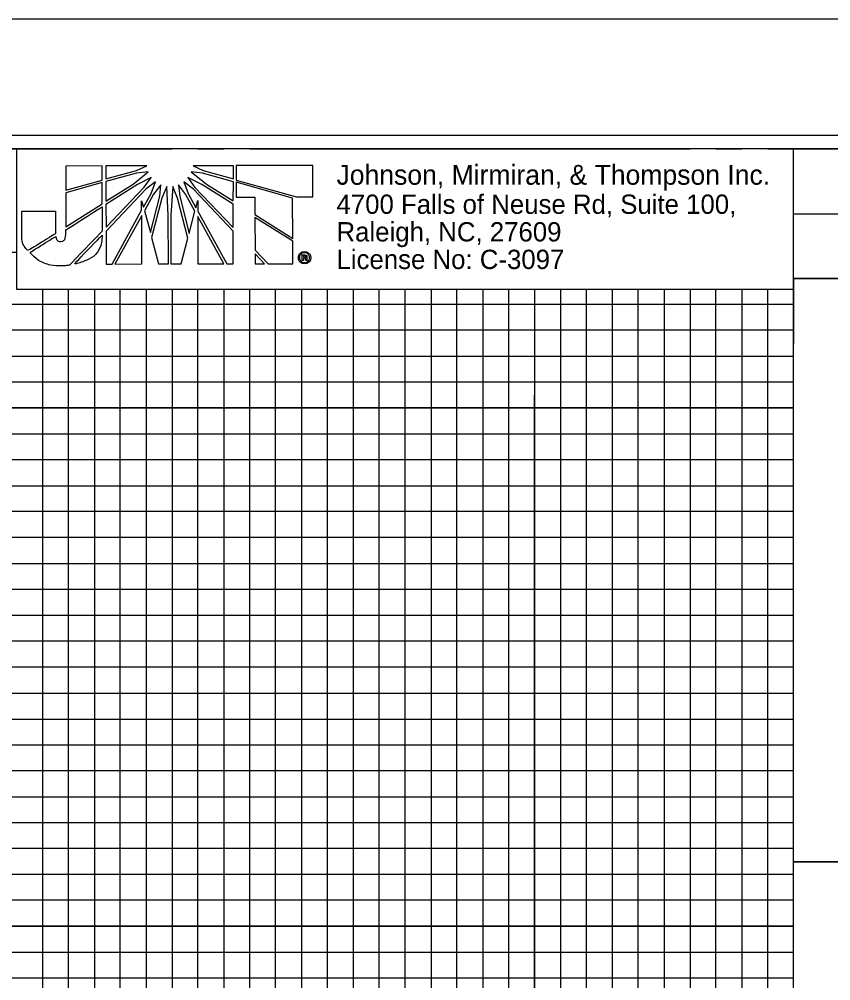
# Model space of a CAD drawing. Extents: x 1648862 to 1650889, y 802691 to 803791.
# Drawn here: x 1650179.8 to 1650336.5, y 803605.5 to 803791 of the extents above; entities that cross this region are included whole.
import ezdxf

# ---------------------------------------------------------------- set-up
doc = ezdxf.new("R2010")
doc.units = 0
for name, color, linetype in [('Prop Dimension Text', 7, 'Continuous'), ('Sheet Cutting Line CELL', 7, 'Continuous'), ('Sheet DOT Grid CELL', 7, 'Continuous'), ('Sheet Plan CELL', 7, 'Continuous'), ('Sheet Plot Border Inside CELL', 7, 'Continuous'), ('Sheet Plot Border Outside CELL', 7, 'Continuous'), ('Sheet Profile CELL', 7, 'Continuous'), ('Sheet Profile Grid Major CELL', 7, 'Continuous'), ('Sheet Profile Grid Middle CELL', 7, 'Continuous'), ('Sheet Profile Grid Minor CELL', 7, 'Continuous'), ('Sheet Sticker Exception Certification CELL', 7, 'Continuous')]:
    doc.layers.add(name, color=color, linetype=linetype)

msp = doc.modelspace()

# ---------------------------------------------------------------- linework, layer by layer
at = {"layer": 'Prop Dimension Text'}
for p, q in [((1650195.79, 803762.71), (1650188.77, 803762.7)), ((1650188.77, 803762.7), (1650188.77, 803758.05)), ((1650195.79, 803760), (1650195.79, 803762.71)), ((1650204.41, 803762.75), (1650196.52, 803762.75)), ((1650196.52, 803762.75), (1650196.52, 803760.23)), ((1650196.52, 803760.23), (1650202.4, 803761.86)), ((1650202.4, 803761.31), (1650196.52, 803759.69)), ((1650201.79, 803759.23), (1650204.69, 803761.59)), ((1650202.4, 803761.86), (1650204.41, 803762.75)), ((1650204.69, 803761.59), (1650202.4, 803761.31)), ((1650212.96, 803761.6), (1650215.9, 803759.2)), ((1650215.13, 803761.33), (1650212.96, 803761.6)), ((1650221.14, 803762.73), (1650213.35, 803762.76)), ((1650213.35, 803762.76), (1650215.32, 803761.84)), ((1650221.14, 803759.68), (1650215.13, 803761.33)), ((1650215.32, 803761.84), (1650221.14, 803760.21)), ((1650221.14, 803760.21), (1650221.14, 803762.73)), ((1650236.43, 803762.78), (1650221.68, 803762.77)), ((1650221.68, 803762.77), (1650221.68, 803760.06)), ((1650236.44, 803756.74), (1650236.43, 803762.78)), ((1650188.77, 803758.05), (1650195.79, 803760)), ((1650195.79, 803759.49), (1650188.77, 803757.52)), ((1650195.79, 803755.43), (1650195.79, 803759.49)), ((1650196.52, 803759.69), (1650196.52, 803755.89)), ((1650205.27, 803760.51), (1650202.6, 803759.15)), ((1650203.92, 803758.61), (1650205.27, 803760.51)), ((1650206.08, 803759.66), (1650204.22, 803758.22)), ((1650205.23, 803757.42), (1650206.08, 803759.66)), ((1650211.53, 803759.67), (1650212.39, 803757.42)), ((1650213.39, 803758.23), (1650211.53, 803759.67)), ((1650212.35, 803760.51), (1650213.71, 803758.58)), ((1650215.06, 803759.16), (1650212.35, 803760.51)), ((1650221.1, 803755.96), (1650221.14, 803759.68)), ((1650221.68, 803760.06), (1650221.68, 803759.98)), ((1650221.68, 803759.98), (1650233.3, 803756.74)), ((1650221.68, 803759.56), (1650221.68, 803759.52)), ((1650232.56, 803756.47), (1650221.68, 803759.56)), ((1650221.68, 803759.52), (1650221.69, 803756.69)), ((1650188.77, 803757.52), (1650188.78, 803750.97)), ((1650196.52, 803755.89), (1650201.79, 803759.23)), ((1650202.6, 803759.15), (1650196.52, 803755.28)), ((1650196.53, 803750.9), (1650203.92, 803758.61)), ((1650204.22, 803758.22), (1650196.53, 803750.16)), ((1650203.76, 803754.74), (1650205.23, 803757.42)), ((1650207.09, 803759.04), (1650205.7, 803757.25)), ((1650206.9, 803756.87), (1650207.09, 803759.04)), ((1650208.25, 803758.73), (1650207.29, 803756.48)), ((1650208.56, 803753.19), (1650208.25, 803758.73)), ((1650209.41, 803758.73), (1650209.05, 803753.19)), ((1650210.34, 803756.48), (1650209.41, 803758.73)), ((1650210.53, 803759.04), (1650210.77, 803756.8)), ((1650211.89, 803757.26), (1650210.53, 803759.04)), ((1650212.39, 803757.42), (1650213.89, 803754.63)), ((1650221.1, 803750.11), (1650213.39, 803758.23)), ((1650213.71, 803758.58), (1650221.1, 803750.84)), ((1650221.1, 803755.33), (1650215.06, 803759.16)), ((1650215.9, 803759.2), (1650221.1, 803755.96)), ((1650203.41, 803754.16), (1650203.41, 803756.01)), ((1650203.41, 803756.01), (1650203.76, 803754.74)), ((1650205.7, 803757.25), (1650203.96, 803754.08)), ((1650205.09, 803749.87), (1650206.9, 803756.87)), ((1650207.29, 803756.48), (1650205.32, 803748.89)), ((1650212.36, 803748.78), (1650210.34, 803756.48)), ((1650210.77, 803756.8), (1650212.59, 803749.71)), ((1650213.71, 803753.97), (1650211.89, 803757.26)), ((1650213.89, 803754.63), (1650214.25, 803756.02)), ((1650214.25, 803756.02), (1650214.25, 803753.97)), ((1650221.69, 803756.69), (1650225.29, 803756.69)), ((1650225.29, 803756.69), (1650225.29, 803753.32)), ((1650232.57, 803748.72), (1650232.56, 803756.47)), ((1650233.3, 803756.74), (1650236.44, 803756.74)), ((1650188.78, 803750.97), (1650195.79, 803755.43)), ((1650196.52, 803755.28), (1650196.53, 803750.9)), ((1650197.69, 803743.79), (1650203.41, 803754.16)), ((1650203.96, 803754.08), (1650205.09, 803749.87)), ((1650212.59, 803749.71), (1650213.71, 803753.97)), ((1650214.25, 803753.97), (1650219.87, 803743.81)), ((1650221.1, 803750.84), (1650221.1, 803755.33)), ((1650203.42, 803753.15), (1650198.24, 803743.79)), ((1650203.47, 803743.8), (1650203.42, 803753.15)), ((1650208.57, 803743.84), (1650208.56, 803753.19)), ((1650209.05, 803753.19), (1650209.06, 803743.84)), ((1650219.29, 803743.85), (1650214.25, 803752.97)), ((1650214.25, 803752.97), (1650214.26, 803743.84)), ((1650225.29, 803753.32), (1650232.57, 803748.72)), ((1650225.29, 803752.74), (1650225.3, 803746.47)), ((1650232.57, 803748.18), (1650225.29, 803752.74)), ((1650196.53, 803750.16), (1650196.53, 803743.79)), ((1650221.11, 803743.81), (1650221.1, 803750.11)), ((1650205.32, 803748.89), (1650206.64, 803743.83)), ((1650211.01, 803743.84), (1650212.36, 803748.78)), ((1650232.57, 803743.82), (1650232.57, 803748.18)), ((1650225.3, 803746.47), (1650227.81, 803743.82)), ((1650227.12, 803743.82), (1650225.3, 803745.78)), ((1650225.3, 803745.78), (1650225.3, 803743.82)), ((1650234.42, 803744.49), (1650234.42, 803745.56)), ((1650234.42, 803745.56), (1650234.86, 803745.56)), ((1650234.66, 803744.49), (1650234.42, 803744.49)), ((1650234.86, 803745.36), (1650234.66, 803745.36)), ((1650234.66, 803745.36), (1650234.66, 803745.1)), ((1650234.66, 803745.1), (1650234.86, 803745.1)), ((1650234.86, 803744.91), (1650234.66, 803744.91)), ((1650234.66, 803744.91), (1650234.66, 803744.49)), ((1650234.86, 803746.19), (1650234.86, 803745.97)), ((1650234.86, 803745.97), (1650234.86, 803746.19)), ((1650234.86, 803745.56), (1650234.86, 803745.36)), ((1650234.86, 803745.36), (1650234.86, 803745.56)), ((1650234.86, 803745.56), (1650234.92, 803745.56)), ((1650234.89, 803745.36), (1650234.86, 803745.36)), ((1650234.86, 803745.1), (1650234.86, 803744.91)), ((1650234.86, 803744.91), (1650234.86, 803745.1)), ((1650234.86, 803745.1), (1650234.87, 803745.1)), ((1650234.87, 803744.91), (1650234.86, 803744.91)), ((1650196.53, 803743.79), (1650197.69, 803743.79)), ((1650198.24, 803743.79), (1650203.47, 803743.8)), ((1650206.64, 803743.83), (1650208.57, 803743.84)), ((1650209.06, 803743.84), (1650211.01, 803743.84)), ((1650214.26, 803743.84), (1650219.29, 803743.85)), ((1650219.87, 803743.81), (1650221.11, 803743.81)), ((1650225.3, 803743.82), (1650227.12, 803743.82)), ((1650227.81, 803743.82), (1650232.57, 803743.82)), ((1650234.86, 803744.07), (1650234.86, 803743.83)), ((1650234.86, 803743.83), (1650234.86, 803744.07)), ((1650234.86, 803744.07), (1650234.87, 803744.07)), ((1650234.87, 803743.83), (1650234.86, 803743.83))]:
    msp.add_line(p, q, dxfattribs=at)
msp.add_lwpolyline([(1650179.28, 803738.96), (1650329.23, 803738.96), (1650329.23, 803766.02), (1650179.28, 803766.02)], close=True, dxfattribs=at)
for points in [[(1650188.77, 803758.05), (1650195.79, 803760), (1650195.79, 803762.71), (1650188.77, 803762.7), (1650188.77, 803758.05)], [(1650202.4, 803761.86), (1650204.41, 803762.75), (1650196.52, 803762.75), (1650196.52, 803760.23), (1650202.4, 803761.86)], [(1650196.52, 803759.69), (1650196.52, 803755.89), (1650201.79, 803759.23), (1650204.69, 803761.59), (1650202.4, 803761.31), (1650196.52, 803759.69)], [(1650212.96, 803761.6), (1650215.9, 803759.2), (1650221.1, 803755.96), (1650221.14, 803759.68), (1650215.13, 803761.33), (1650212.96, 803761.6)], [(1650215.32, 803761.84), (1650221.14, 803760.21), (1650221.14, 803762.73), (1650213.35, 803762.76), (1650215.32, 803761.84)], [(1650236.43, 803762.78), (1650221.68, 803762.77), (1650221.68, 803760.06), (1650221.68, 803759.98), (1650233.3, 803756.74), (1650236.44, 803756.74), (1650236.43, 803762.78)], [(1650188.78, 803750.97), (1650195.79, 803755.43), (1650195.79, 803759.49), (1650188.77, 803757.52), (1650188.78, 803750.97)], [(1650196.52, 803755.28), (1650196.53, 803750.9), (1650203.92, 803758.61), (1650205.27, 803760.51), (1650202.6, 803759.15), (1650196.52, 803755.28)], [(1650206.08, 803759.66), (1650204.22, 803758.22), (1650196.53, 803750.16), (1650196.53, 803743.79), (1650197.69, 803743.79), (1650203.41, 803754.16), (1650203.41, 803756.01), (1650203.76, 803754.74), (1650205.23, 803757.42), (1650206.08, 803759.66)], [(1650211.53, 803759.67), (1650212.39, 803757.42), (1650213.89, 803754.63), (1650214.25, 803756.02), (1650214.25, 803753.97), (1650219.87, 803743.81), (1650221.11, 803743.81), (1650221.1, 803750.11), (1650213.39, 803758.23), (1650211.53, 803759.67)], [(1650212.35, 803760.51), (1650213.71, 803758.58), (1650221.1, 803750.84), (1650221.1, 803755.33), (1650215.06, 803759.16), (1650212.35, 803760.51)], [(1650221.68, 803759.56), (1650221.68, 803759.52), (1650221.69, 803756.69), (1650225.29, 803756.69), (1650225.29, 803753.32), (1650232.57, 803748.72), (1650232.56, 803756.47), (1650221.68, 803759.56)], [(1650207.09, 803759.04), (1650205.7, 803757.25), (1650203.96, 803754.08), (1650205.09, 803749.87), (1650206.9, 803756.87), (1650207.09, 803759.04)], [(1650207.29, 803756.48), (1650205.32, 803748.89), (1650206.64, 803743.83), (1650208.57, 803743.84), (1650208.56, 803753.19), (1650208.25, 803758.73), (1650207.29, 803756.48)], [(1650209.41, 803758.73), (1650209.05, 803753.19), (1650209.06, 803743.84), (1650211.01, 803743.84), (1650212.36, 803748.78), (1650210.34, 803756.48), (1650209.41, 803758.73)], [(1650210.53, 803759.04), (1650210.77, 803756.8), (1650212.59, 803749.71), (1650213.71, 803753.97), (1650211.89, 803757.26), (1650210.53, 803759.04)], [(1650198.24, 803743.79), (1650203.47, 803743.8), (1650203.42, 803753.15), (1650198.24, 803743.79)], [(1650214.26, 803743.84), (1650219.29, 803743.85), (1650214.25, 803752.97), (1650214.26, 803743.84)], [(1650225.29, 803752.74), (1650225.3, 803746.47), (1650227.81, 803743.82), (1650232.57, 803743.82), (1650232.57, 803748.18), (1650225.29, 803752.74), (1650225.29, 803752.74)], [(1650225.3, 803743.82), (1650225.3, 803743.82), (1650227.12, 803743.82), (1650225.3, 803745.78), (1650225.3, 803743.82)], [(1650235.33, 803744.74), (1650235.33, 803744.68), (1650235.33, 803744.64), (1650235.33, 803744.61), (1650235.36, 803744.49), (1650235.14, 803744.49)]]:
    msp.add_lwpolyline(points, dxfattribs=at)
for points, degree in [([(1650186.76, 803753.98), (1650186.76, 803753.98), (1650180.27, 803753.98), (1650180.27, 803753.98), (1650180.27, 803753.98), (1650180.27, 803749.91), (1650180.27, 803749.91), (1650180.27, 803749.91), (1650180.27, 803749.48), (1650180.27, 803749.48), (1650180.27, 803748.21), (1650180.69, 803747.2), (1650181.43, 803746.36), (1650181.43, 803746.36), (1650186.77, 803749.6), (1650186.77, 803749.69), (1650186.77, 803749.69), (1650186.76, 803753.98), (1650186.76, 803753.98)], 3), ([(1650187.78, 803748.13), (1650187.36, 803748.13), (1650187, 803748.37), (1650186.85, 803749.14), (1650186.85, 803749.14), (1650181.81, 803746.02), (1650181.81, 803746.02), (1650183.37, 803744.39), (1650185.85, 803743.42), (1650187.94, 803743.42), (1650188.49, 803743.42), (1650188.9, 803743.47), (1650189.48, 803743.59), (1650189.48, 803743.59), (1650195.8, 803750.12), (1650195.8, 803750.12), (1650195.8, 803750.12), (1650195.79, 803754.85), (1650195.79, 803754.85), (1650195.79, 803754.85), (1650188.78, 803750.38), (1650188.78, 803750.38), (1650188.78, 803748.61), (1650188.35, 803748.14), (1650187.78, 803748.13)], 3), ([(1650187.78, 803748.13), (1650187.36, 803748.13), (1650187, 803748.37), (1650186.85, 803749.14), (1650186.85, 803749.14), (1650181.81, 803746.02), (1650181.81, 803746.02), (1650183.37, 803744.39), (1650185.85, 803743.42), (1650187.94, 803743.42), (1650188.49, 803743.42), (1650188.9, 803743.47), (1650189.48, 803743.59), (1650189.48, 803743.59), (1650195.8, 803750.12), (1650195.8, 803750.12), (1650195.8, 803750.12), (1650195.79, 803754.85), (1650195.79, 803754.85), (1650195.79, 803754.85), (1650188.78, 803750.38), (1650188.78, 803750.38), (1650188.78, 803748.61), (1650188.35, 803748.14), (1650187.78, 803748.13)], 3), ([(1650195.8, 803749.38), (1650195.8, 803749.38), (1650190.34, 803743.74), (1650190.34, 803743.74), (1650193.01, 803744.4), (1650195.68, 803746.17), (1650195.8, 803749.38)], 3), ([(1650234.86, 803743.83), (1650234.54, 803743.83), (1650234.25, 803743.95), (1650234.02, 803744.18), (1650233.78, 803744.41), (1650233.67, 803744.69), (1650233.67, 803745.02), (1650233.67, 803745.35), (1650233.78, 803745.64), (1650234.02, 803745.85), (1650234.25, 803746.08), (1650234.52, 803746.19), (1650234.86, 803746.19)], 3), ([(1650234.86, 803745.97), (1650234.59, 803745.97), (1650234.37, 803745.88), (1650234.18, 803745.71), (1650234, 803745.52), (1650233.9, 803745.29), (1650233.9, 803745.02), (1650233.9, 803744.76), (1650234, 803744.53), (1650234.18, 803744.34), (1650234.37, 803744.16), (1650234.59, 803744.07), (1650234.86, 803744.07)], 3), ([(1650234.86, 803746.19), (1650235.19, 803746.19), (1650235.47, 803746.08), (1650235.7, 803745.85), (1650235.94, 803745.64), (1650236.06, 803745.36), (1650236.06, 803745.03)], 3), ([(1650234.87, 803744.07), (1650235.13, 803744.07), (1650235.35, 803744.16), (1650235.54, 803744.34), (1650235.72, 803744.53), (1650235.82, 803744.76), (1650235.82, 803745.03), (1650235.82, 803745.29), (1650235.72, 803745.52), (1650235.54, 803745.71), (1650235.35, 803745.88), (1650235.13, 803745.97), (1650234.86, 803745.97)], 3), ([(1650234.87, 803745.1), (1650235.02, 803745.1), (1650235.1, 803745.15), (1650235.1, 803745.24), (1650235.1, 803745.32), (1650235.03, 803745.36), (1650234.89, 803745.36)], 3), ([(1650236.06, 803745.03), (1650236.06, 803744.69), (1650235.94, 803744.41), (1650235.72, 803744.18), (1650235.48, 803743.95), (1650235.2, 803743.83), (1650234.87, 803743.83)], 3), ([(1650235.05, 803744.87), (1650235.02, 803744.89), (1650234.96, 803744.91), (1650234.87, 803744.91)], 2), ([(1650234.92, 803745.56), (1650235.2, 803745.56), (1650235.33, 803745.45), (1650235.33, 803745.24), (1650235.33, 803745.14), (1650235.3, 803745.06), (1650235.21, 803745)], 3), ([(1650235.14, 803744.49), (1650235.11, 803744.55), (1650235.09, 803744.61), (1650235.09, 803744.68), (1650235.09, 803744.78), (1650235.08, 803744.84), (1650235.05, 803744.87)], 3), ([(1650235.21, 803745), (1650235.28, 803744.97), (1650235.32, 803744.88), (1650235.33, 803744.74)], 2)]:
    msp.add_open_spline(points, degree=degree, dxfattribs=at)
at = {"layer": 'Sheet Cutting Line CELL'}
msp.add_line((1650546.28, 803791.02), (1648862.28, 803791.02), dxfattribs=at)
at = {"layer": 'Sheet DOT Grid CELL'}
for p, q in [((1650229.28, 803266.02), (1650229.28, 803718.48)), ((1650279.28, 803266.02), (1650279.28, 803718.48)), ((1650329.23, 803716.02), (1649029.28, 803716.02)), ((1650329.23, 803666.02), (1649029.28, 803666.02)), ((1650329.28, 803266.02), (1650329.28, 803628.47)), ((1650329.28, 803616.02), (1649029.28, 803616.02))]:
    msp.add_line(p, q, dxfattribs=at)
at = {"layer": 'Sheet Plan CELL'}
msp.add_line((1650329.23, 803740.94), (1650329.23, 803728.45), dxfattribs=at)
msp.add_line((1650329.23, 803740.94), (1650329.23, 803728.45), dxfattribs=at)
msp.add_line((1650329.23, 803740.94), (1650329.23, 803728.45), dxfattribs=at)
at = {"layer": 'Sheet Plot Border Inside CELL'}
msp.add_lwpolyline([(1648875.28, 802713.47), (1650541.78, 802713.47), (1650541.78, 803768.57), (1648875.28, 803768.57)], close=True, dxfattribs=at)
at = {"layer": 'Sheet Plot Border Outside CELL'}
msp.add_lwpolyline([(1648862.28, 802691.02), (1650546.28, 802691.02), (1650546.28, 803791.02), (1648862.28, 803791.02)], close=True, dxfattribs=at)
at = {"layer": 'Sheet Profile CELL'}
msp.add_line((1650329.23, 803753.47), (1650529.28, 803753.47), dxfattribs=at)
for points in [[(1650529.28, 803766.02), (1649029.28, 803766.02), (1649029.28, 802716.02), (1650529.28, 802716.02)], [(1650329.23, 803766.02), (1650529.28, 803766.02), (1650529.28, 803740.97), (1650329.23, 803740.97)], [(1650329.23, 803740.97), (1650429.28, 803740.97), (1650429.28, 803628.47), (1650329.23, 803628.47)]]:
    msp.add_lwpolyline(points, close=True, dxfattribs=at)
at = {"layer": 'Sheet Profile Grid Major CELL'}
for points in [[(1650229.28, 803766.02), (1650279.28, 803766.02)], [(1650279.28, 803738.96), (1650279.28, 803266.02), (1650329.28, 803266.02), (1650329.28, 803766.02), (1650355.58, 803766.02)], [(1650179.28, 803266.02), (1650229.28, 803266.02), (1650229.28, 803738.96)], [(1649029.28, 803716.02), (1650329.28, 803716.02)], [(1650329.28, 803666.02), (1649029.28, 803666.02), (1649029.28, 803616.02), (1650329.28, 803616.02)]]:
    msp.add_lwpolyline(points, dxfattribs=at)
at = {"layer": 'Sheet Profile Grid Middle CELL'}
for points in [[(1650154.28, 803766.02), (1650204.28, 803766.02)], [(1650254.28, 803766.02), (1650304.28, 803766.02)], [(1650204.28, 803738.96), (1650204.28, 803266.02), (1650254.28, 803266.02), (1650254.28, 803738.96)], [(1650304.28, 803738.96), (1650304.28, 803266.02), (1650354.28, 803266.02), (1650354.28, 803604.97)], [(1650329.28, 803691.02), (1649029.28, 803691.02), (1649029.28, 803641.02), (1650329.28, 803641.02)]]:
    msp.add_lwpolyline(points, dxfattribs=at)
at = {"layer": 'Sheet Profile Grid Minor CELL'}
for p, q in [((1650329.23, 803761.02), (1650329.28, 803761.02)), ((1650329.28, 803756.02), (1650329.23, 803756.02)), ((1650329.23, 803751.02), (1650329.28, 803751.02)), ((1650329.23, 803631.02), (1649079.28, 803631.02)), ((1650329.28, 803626.02), (1649079.28, 803626.02)), ((1650329.28, 803621.02), (1649079.28, 803621.02)), ((1649079.28, 803611.02), (1650329.28, 803611.02)), ((1650329.28, 803606.02), (1649079.28, 803606.02))]:
    msp.add_line(p, q, dxfattribs=at)
for points in [[(1650174.28, 803766.02), (1650184.28, 803766.02)], [(1650189.28, 803766.02), (1650194.28, 803766.02)], [(1650199.28, 803766.02), (1650209.28, 803766.02)], [(1650214.28, 803766.02), (1650219.28, 803766.02)], [(1650224.28, 803766.02), (1650234.28, 803766.02)], [(1650239.28, 803766.02), (1650244.28, 803766.02)], [(1650249.28, 803766.02), (1650259.28, 803766.02)], [(1650264.28, 803766.02), (1650269.28, 803766.02)], [(1650274.28, 803766.02), (1650284.28, 803766.02)], [(1650289.28, 803766.02), (1650294.28, 803766.02)], [(1650299.28, 803766.02), (1650309.28, 803766.02)], [(1650314.28, 803766.02), (1650319.28, 803766.02)], [(1650324.28, 803766.02), (1650334.28, 803766.02)], [(1650179.28, 803746.02), (1649079.28, 803746.02), (1649079.28, 803736.02), (1650329.28, 803736.02)], [(1650329.28, 803746.02), (1650329.23, 803746.02)], [(1650184.28, 803738.96), (1650184.28, 803266.02), (1650189.28, 803266.02), (1650189.28, 803738.96)], [(1650194.28, 803738.96), (1650194.28, 803266.02), (1650199.28, 803266.02), (1650199.28, 803738.96)], [(1650209.28, 803738.96), (1650209.28, 803266.02), (1650214.28, 803266.02), (1650214.28, 803738.96)], [(1650219.28, 803266.02), (1650224.28, 803266.02), (1650224.28, 803738.96)], [(1650219.28, 803738.96), (1650219.28, 803266.02)], [(1650234.28, 803738.96), (1650234.28, 803266.02), (1650239.28, 803266.02), (1650239.28, 803738.96)], [(1650244.28, 803738.96), (1650244.28, 803266.02), (1650249.28, 803266.02), (1650249.28, 803738.96)], [(1650259.28, 803738.96), (1650259.28, 803266.02), (1650264.28, 803266.02), (1650264.28, 803738.96)], [(1650269.28, 803738.96), (1650269.28, 803266.02), (1650274.28, 803266.02), (1650274.28, 803738.96)], [(1650284.28, 803738.96), (1650284.28, 803266.02), (1650289.28, 803266.02), (1650289.28, 803738.96)], [(1650294.28, 803738.96), (1650294.28, 803266.02), (1650299.28, 803266.02), (1650299.28, 803738.96)], [(1650309.28, 803738.96), (1650309.28, 803266.02), (1650314.28, 803266.02), (1650314.28, 803738.96)], [(1650319.28, 803738.96), (1650319.28, 803266.02), (1650324.28, 803266.02), (1650324.28, 803738.96)], [(1650329.23, 803731.02), (1649079.28, 803731.02), (1649079.28, 803726.02), (1650329.28, 803726.02)], [(1650329.28, 803721.02), (1649079.28, 803721.02), (1649079.28, 803711.02), (1650329.28, 803711.02)], [(1650329.28, 803706.02), (1649079.28, 803706.02), (1649079.28, 803701.02), (1650329.28, 803701.02)], [(1650329.28, 803696.02), (1649079.28, 803696.02), (1649079.28, 803686.02), (1650329.28, 803686.02)], [(1650329.28, 803681.02), (1649079.28, 803681.02), (1649079.28, 803676.02), (1650329.28, 803676.02)], [(1650329.28, 803671.02), (1649079.28, 803671.02), (1649079.28, 803661.02), (1650329.28, 803661.02)], [(1650329.28, 803655.92), (1649079.38, 803655.92), (1649079.38, 803651.02), (1650329.28, 803651.02)], [(1650329.28, 803646.02), (1649079.28, 803646.02), (1649079.28, 803636.02), (1650329.28, 803636.02)]]:
    msp.add_lwpolyline(points, dxfattribs=at)
at = {"layer": 'Sheet Sticker Exception Certification CELL'}
for p, q in [((1650329.23, 803604.97), (1650329.23, 803628.47)), ((1650329.23, 803628.47), (1650529.27, 803628.47)), ((1650329.23, 803604.97), (1650329.23, 803628.47)), ((1650329.23, 803628.47), (1650529.27, 803628.47))]:
    msp.add_line(p, q, dxfattribs=at)

# ---------------------------------------------------------------- texts
at = {"layer": 'Prop Dimension Text'}
for s, height, p in [('Johnson, Mirmiran, & Thompson Inc.', 3.8315, (1650241.03, 803759.09)), ('4700 Falls of Neuse Rd, Suite 100, ', 3.722, (1650241.03, 803753.47)), ('Raleigh, NC, 27609', 3.722, (1650241.03, 803748.15)), ('License No: C-3097', 3.722, (1650241.03, 803742.83))]:
    msp.add_text(s, height=height, rotation=360, dxfattribs=at).set_placement(p)

doc.saveas('drawing.dxf')
